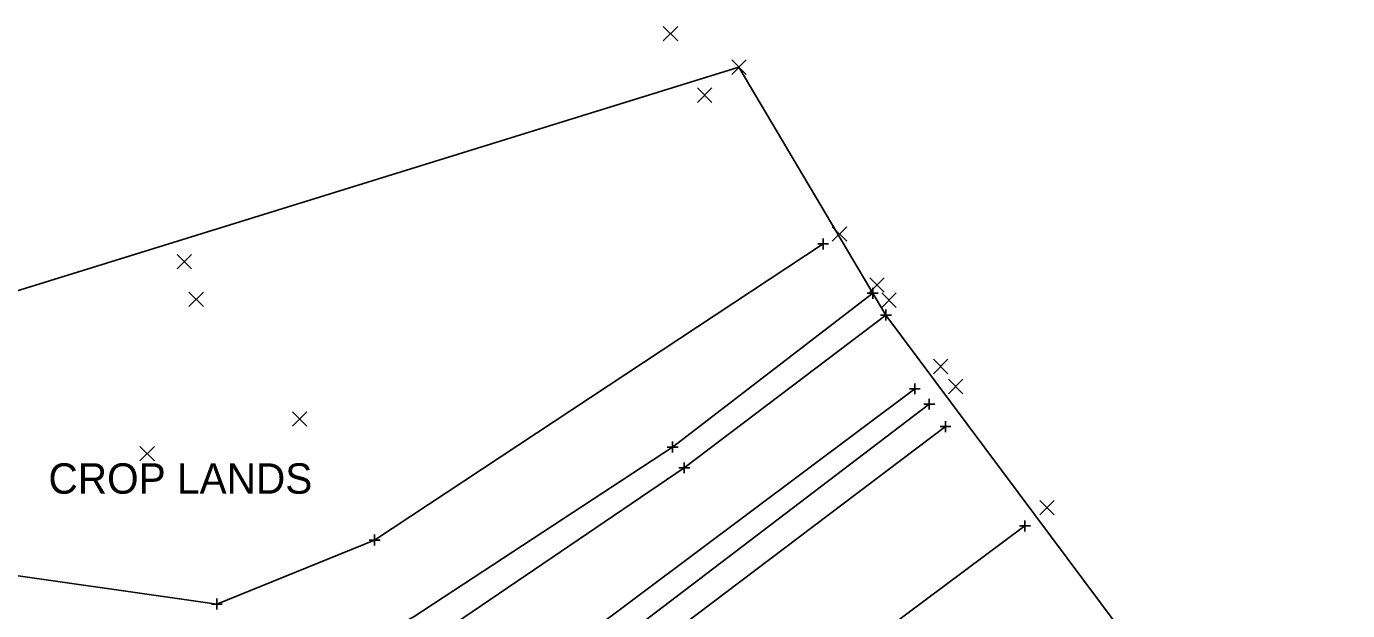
# Model space of a CAD drawing. Extents: x 120332 to 120776, y 463407 to 463745.
# Drawn here: x 120461.5 to 120583.4, y 463605.2 to 463659 of the extents above; entities that cross this region are included whole.
import ezdxf

# ---------------------------------------------------------------- set-up
doc = ezdxf.new("R2010")
doc.units = 0
for name, color, linetype in [('Default', 7, 'Continuous'), ('GE_X_Alignment', 7, 'Continuous'), ('GE_X_Alignment_100_Bearings', 7, 'Continuous'), ('GE_X_Alignment_100_Cardinal_Points', 7, 'Continuous'), ('GE_X_Alignment_100_Distances', 7, 'Continuous'), ('GE_X_Alignment_100_Stations', 7, 'Continuous'), ('RD_X_RR_Cells', 7, 'Continuous'), ('SV_P_Control_Cells_Set', 7, 'Continuous'), ('SV_P_Mon_Cells_Set', 7, 'Continuous'), ('SV_X_Mon_Cells_Found', 7, 'Continuous'), ('SV_X_Random_Point', 7, 'Continuous'), ('SV_X_Terrain_Boundary', 7, 'Continuous')]:
    doc.layers.add(name, color=color, linetype=linetype)

msp = doc.modelspace()

# ---------------------------------------------------------------- linework, layer by layer
at = {"layer": 'GE_X_Alignment'}
msp.add_lwpolyline([(120543.45, 463625.61), (120502.74, 463595.17), (120482.09, 463579.11), (120464.32, 463565.8), (120441.86, 463549.38), (120424.38, 463535.76), (120383.06, 463505.19)], dxfattribs=at)
at = {"layer": 'GE_X_Alignment_100_Bearings'}
msp.add_lwpolyline([(120544.78, 463624.2), (120504.28, 463593.4), (120483.22, 463577.47), (120465.62, 463564.72), (120443.3, 463547.76), (120425.65, 463534.4), (120384.72, 463503.19)], dxfattribs=at)
at = {"layer": 'GE_X_Alignment_100_Cardinal_Points'}
for points in [[(120546.27, 463622.13), (120505.75, 463591.54), (120484.55, 463575.45), (120386.09, 463501.54)], [(120392.05, 463491.7), (120434.29, 463523.26), (120458.68, 463541.48), (120471.62, 463551.86), (120496.01, 463569.76), (120511.36, 463581.53), (120553.61, 463612.98)]]:
    msp.add_lwpolyline(points, dxfattribs=at)
at = {"layer": 'GE_X_Alignment_100_Distances'}
msp.add_lwpolyline([(120392.05, 463491.7), (120434.29, 463523.26), (120458.68, 463541.48), (120471.62, 463551.86), (120496.01, 463569.76), (120511.36, 463581.53), (120553.61, 463612.98)], dxfattribs=at)
at = {"layer": 'GE_X_Alignment_100_Stations'}
msp.add_lwpolyline([(120546.27, 463622.13), (120505.75, 463591.54), (120484.55, 463575.45), (120467.37, 463562.71), (120444.55, 463545.45), (120427.07, 463532.49), (120386.09, 463501.54)], dxfattribs=at)
at = {"layer": 'RD_X_RR_Cells'}
msp.add_lwpolyline([(120421.56, 463619.93), (120426.3, 463612.62), (120436.47, 463605.12), (120443.17, 463597.87), (120449.32, 463591.39), (120456.91, 463583.55), (120459.12, 463582.05), (120462.23, 463580.42), (120466.75, 463584.83), (120476.93, 463591.15), (120482.16, 463596.63), (120497.16, 463604.58), (120521.1, 463620.25), (120539.56, 463634.42)], dxfattribs=at)
at = {"layer": 'SV_P_Control_Cells_Set'}
for p, q in [((120520.23, 463657.67), (120521.57, 463659.01)), ((120520.23, 463659.01), (120521.57, 463657.67)), ((120526.55, 463654.58), (120527.88, 463655.92)), ((120526.55, 463655.92), (120527.88, 463654.58)), ((120523.39, 463652.01), (120524.72, 463653.34)), ((120523.39, 463653.34), (120524.72, 463652.01)), ((120535.82, 463639.21), (120537.16, 463640.54)), ((120535.82, 463640.54), (120537.16, 463639.21)), ((120475.39, 463636.66), (120476.72, 463638)), ((120475.39, 463638), (120476.72, 463636.66)), ((120539.29, 463634.51), (120540.63, 463635.84)), ((120539.29, 463635.84), (120540.63, 463634.51)), ((120476.48, 463633.19), (120477.82, 463634.52)), ((120476.48, 463634.52), (120477.82, 463633.19)), ((120540.39, 463633.12), (120541.72, 463634.45)), ((120540.39, 463634.45), (120541.72, 463633.12)), ((120545.16, 463627.01), (120546.5, 463628.35)), ((120545.16, 463628.35), (120546.5, 463627.01)), ((120546.54, 463625.15), (120547.87, 463626.49)), ((120546.54, 463626.49), (120547.87, 463625.15)), ((120486.03, 463622.16), (120487.36, 463623.5)), ((120486.03, 463623.5), (120487.36, 463622.16)), ((120471.95, 463618.97), (120473.29, 463620.31)), ((120471.95, 463620.31), (120473.29, 463618.97)), ((120554.98, 463614), (120556.31, 463615.33)), ((120554.98, 463615.33), (120556.31, 463614))]:
    msp.add_line(p, q, dxfattribs=at)
at = {"layer": 'SV_P_Mon_Cells_Set'}
msp.add_lwpolyline([(120424.21, 463629.5), (120455.74, 463609.1), (120479.05, 463605.78), (120493.61, 463611.68), (120534.99, 463638.96)], dxfattribs=at)
at = {"layer": 'SV_X_Mon_Cells_Found'}
for p, q in [((120534.49, 463638.96), (120535.49, 463638.96)), ((120534.99, 463639.46), (120534.99, 463638.46)), ((120534.99, 463638.96), (120534.99, 463638.96)), ((120539.56, 463634.92), (120539.56, 463633.92)), ((120539.06, 463634.42), (120540.06, 463634.42)), ((120539.56, 463634.42), (120539.56, 463634.42)), ((120540.28, 463632.41), (120541.28, 463632.41)), ((120540.78, 463632.91), (120540.78, 463631.91)), ((120540.78, 463632.41), (120540.78, 463632.41)), ((120542.95, 463625.61), (120543.95, 463625.61)), ((120543.45, 463626.11), (120543.45, 463625.11)), ((120543.45, 463625.61), (120543.45, 463625.61)), ((120544.28, 463624.2), (120545.28, 463624.2)), ((120544.78, 463624.7), (120544.78, 463623.7)), ((120544.78, 463624.2), (120544.78, 463624.2)), ((120546.27, 463622.63), (120546.27, 463621.63)), ((120546.27, 463622.63), (120546.27, 463621.63)), ((120545.77, 463622.13), (120546.77, 463622.13)), ((120545.77, 463622.13), (120546.77, 463622.13)), ((120546.27, 463622.13), (120546.27, 463622.13)), ((120546.27, 463622.13), (120546.27, 463622.13)), ((120520.6, 463620.25), (120521.6, 463620.25)), ((120521.1, 463620.75), (120521.1, 463619.75)), ((120521.1, 463620.25), (120521.1, 463620.25)), ((120522.18, 463618.83), (120522.18, 463617.83)), ((120521.68, 463618.33), (120522.68, 463618.33)), ((120522.18, 463618.33), (120522.18, 463618.33)), ((120553.11, 463612.98), (120554.11, 463612.98)), ((120553.11, 463612.98), (120554.11, 463612.98)), ((120553.61, 463613.48), (120553.61, 463612.48)), ((120553.61, 463613.48), (120553.61, 463612.48)), ((120553.61, 463612.98), (120553.61, 463612.98)), ((120553.61, 463612.98), (120553.61, 463612.98)), ((120493.11, 463611.68), (120494.11, 463611.68)), ((120493.61, 463612.18), (120493.61, 463611.18)), ((120493.61, 463611.68), (120493.61, 463611.68)), ((120478.55, 463605.78), (120479.55, 463605.78)), ((120479.05, 463606.28), (120479.05, 463605.28)), ((120479.05, 463605.78), (120479.05, 463605.78))]:
    msp.add_line(p, q, dxfattribs=at)
at = {"layer": 'SV_X_Random_Point'}
msp.add_lwpolyline([(120456.76, 463573.83), (120460.31, 463575.65), (120464.21, 463577), (120470.14, 463581.09), (120477.81, 463589.12), (120484.83, 463592.51), (120498.59, 463602.34), (120522.18, 463618.33), (120540.78, 463632.41)], dxfattribs=at)
at = {"layer": 'SV_X_Terrain_Boundary'}
msp.add_lwpolyline([(120382.05, 463504.31), (120392.05, 463491.7), (120404.48, 463476.09), (120419.01, 463449.44), (120492.05, 463471.81), (120514.57, 463481.5), (120536.71, 463497.24), (120541.46, 463506.92), (120568.63, 463561.6), (120583.37, 463575.39), (120540.78, 463632.41), (120527.21, 463655.25), (120435.5, 463626.86), (120399.02, 463601.89), (120359.63, 463534.8), (120382.05, 463504.31)], dxfattribs=at)

# ---------------------------------------------------------------- texts
at = {"layer": 'Default'}
msp.add_text('CROP LANDS', height=2.8, dxfattribs=at).set_placement((120463.52, 463615.95))

doc.saveas('drawing.dxf')
